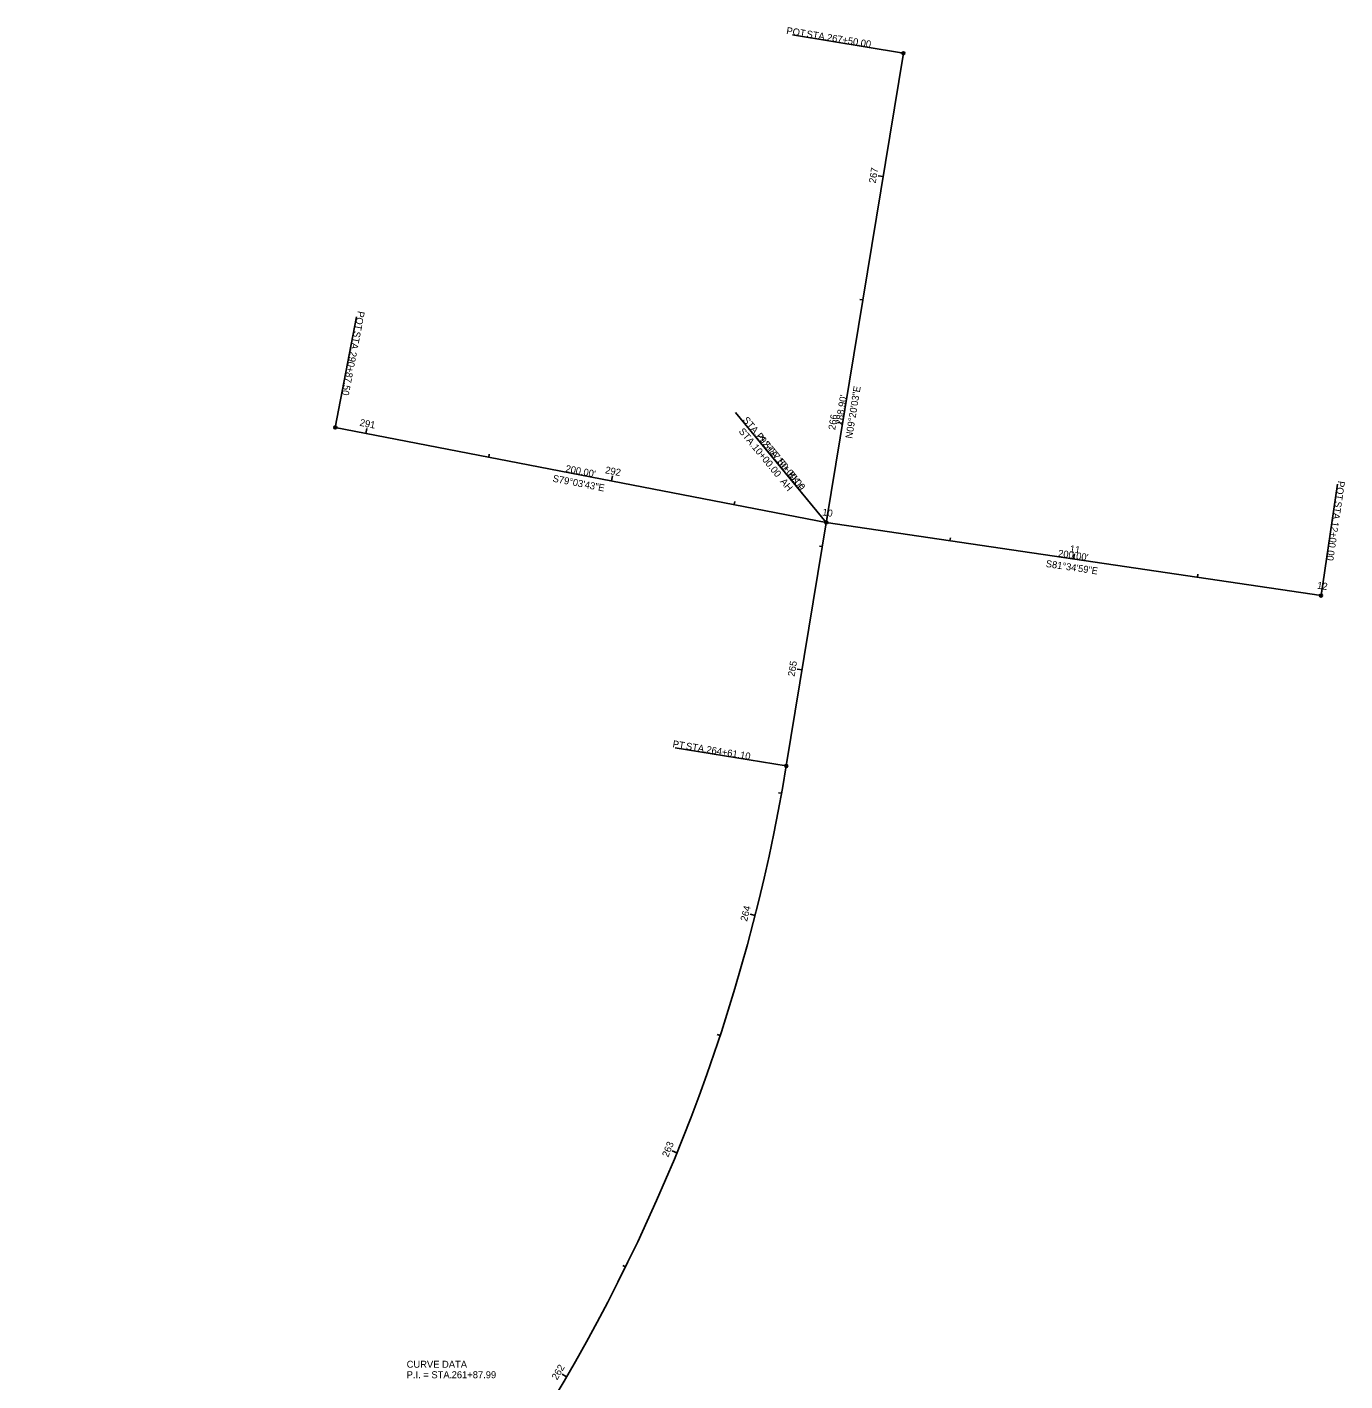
# Model space of a CAD drawing. Extents: x 1481464 to 1482480, y 364592 to 365678.
# Drawn here: x 1481953 to 1482480, y 365137 to 365678 of the extents above; entities that cross this region are included whole.
import ezdxf

# ---------------------------------------------------------------- set-up
doc = ezdxf.new("R2010")
doc.units = 0
for name, color, linetype in [('RD_X_Cells', 7, 'Continuous'), ('SG_X_Poles', 7, 'Continuous'), ('SN_X_Public', 7, 'Continuous'), ('SV_X_Random_Point', 7, 'Continuous'), ('UT_X_Electric_Cells', 7, 'Continuous'), ('UT_X_Misc_Cells', 7, 'Continuous')]:
    doc.layers.add(name, color=color, linetype=linetype)

msp = doc.modelspace()

# ---------------------------------------------------------------- linework, layer by layer
at = {"layer": 'RD_X_Cells'}
for p, q in [((1482303.1, 365667.88), (1482258.7, 365675.18)), ((1482075.9, 365518.19), (1482084.43, 365562.38)), ((1482272.26, 365480.24), (1482236, 365524.22)), ((1482272.26, 365480.24), (1482243.61, 365514.95)), ((1482470.11, 365450.97), (1482476.7, 365495.48)), ((1482256.25, 365382.8), (1482211.84, 365390.1))]:
    msp.add_line(p, q, dxfattribs=at)
for centre in [(1482303.1, 365667.88), (1482075.9, 365518.19), (1482272.26, 365480.24), (1482272.26, 365480.24), (1482470.11, 365450.97), (1482256.25, 365382.8)]:
    msp.add_circle(centre, 0.6, dxfattribs=at)
at = {"layer": 'SG_X_Poles'}
for p, q in [((1482303.1, 365667.88), (1482301.92, 365668.07)), ((1482294.99, 365618.54), (1482293.02, 365618.86)), ((1482286.88, 365569.2), (1482285.7, 365569.4)), ((1482088.17, 365515.82), (1482088.55, 365517.79)), ((1482278.77, 365519.86), (1482276.8, 365520.19)), ((1482137.26, 365506.33), (1482137.49, 365507.51)), ((1482186.35, 365496.85), (1482186.73, 365498.81)), ((1482235.44, 365487.36), (1482235.67, 365488.54)), ((1482272.26, 365480.24), (1482272.56, 365482.22)), ((1482321.72, 365472.93), (1482321.9, 365474.11)), ((1482270.67, 365470.52), (1482269.48, 365470.72)), ((1482371.19, 365465.61), (1482371.48, 365467.59)), ((1482420.65, 365458.29), (1482420.82, 365459.48)), ((1482470.11, 365450.97), (1482470.4, 365452.95)), ((1482262.56, 365421.19), (1482260.58, 365421.51)), ((1482254.36, 365371.86), (1482253.18, 365372.08)), ((1482243.78, 365323.01), (1482241.84, 365323.5)), ((1482229.81, 365275.01), (1482228.67, 365275.38)), ((1482212.53, 365228.1), (1482210.68, 365228.85)), ((1482192.02, 365182.51), (1482190.95, 365183.04)), ((1482168.38, 365138.46), (1482166.66, 365139.47))]:
    msp.add_line(p, q, dxfattribs=at)
at = {"layer": 'UT_X_Misc_Cells'}
for p, q in [((1482256.25, 365382.8), (1482303.1, 365667.88)), ((1482075.9, 365518.19), (1482272.26, 365480.24)), ((1482272.26, 365480.24), (1482470.11, 365450.97))]:
    msp.add_line(p, q, dxfattribs=at)
msp.add_arc((1481549.53, 365498.96), 716.2, 304.25163, 350.66585, dxfattribs=at)

# ---------------------------------------------------------------- texts
at = {"layer": 'RD_X_Cells'}
for s, rotation, p in [('POT', 350.6659, (1482256.14, 365675.63)), (' STA. ', 350.6659, (1482263.17, 365674.48)), ('267+50.00', 350.6659, (1482272.37, 365672.96)), ('POT', 259.062, (1482084.96, 365564.92)), (' STA. ', 259.062, (1482083.61, 365557.92)), ('290+87.50', 259.062, (1482081.84, 365548.77)), ('STA. ', 309.5057, (1482238.64, 365521.09)), ('STA. ', 309.5057, (1482237.07, 365516.56)), ('292+87.50', 309.5057, (1482243.93, 365514.66)), ('PI', 309.5057, (1482243.93, 365514.66)), ('10+00.00', 309.5057, (1482242.37, 365510.14)), (' STA. ', 309.5057, (1482246.04, 365512.1)), ('10+00.00', 309.5057, (1482251.97, 365504.91)), (' BK =', 309.5057, (1482255.97, 365500.06)), (' AH', 309.5057, (1482252.98, 365497.26)), ('POT', 261.5831, (1482476.95, 365496.95)), (' STA. ', 261.5831, (1482475.91, 365489.89)), ('12+00.00', 261.5831, (1482474.54, 365480.67)), ('PT', 350.6659, (1482210.65, 365390.33)), (' STA. ', 350.6659, (1482214.95, 365389.63)), ('264+61.10', 350.6659, (1482224.14, 365388.12))]:
    msp.add_text(s, height=2.8, rotation=rotation, dxfattribs=at).set_placement(p)
at = {"layer": 'SG_X_Poles'}
for s, rotation, p in [('267', 80.6659, (1482292, 365615.74)), ('291', 349.062, (1482085.48, 365518.89)), ('266', 80.6659, (1482275.78, 365517.06)), ('292', 349.062, (1482183.67, 365499.91)), ('10', 351.5831, (1482270.5, 365483.03)), ('11', 351.5831, (1482369.47, 365468.39)), ('12', 351.5831, (1482468.4, 365453.75)), ('265', 80.6659, (1482259.57, 365418.43)), ('264', 75.7779, (1482240.55, 365320.44)), ('263', 67.7779, (1482209.01, 365226.08)), ('262', 59.7779, (1482164.61, 365136.95))]:
    msp.add_text(s, height=2.8, rotation=rotation, dxfattribs=at).set_placement(p)
at = {"layer": 'SN_X_Public'}
for s, p in [('CURVE DATA', (1482104.44, 365142.09)), ('P.I. = STA. ', (1482104.44, 365137.89)), ('261+87.99', (1482122.43, 365137.89))]:
    msp.add_text(s, height=2.8, dxfattribs=at).set_placement(p)
at = {"layer": 'SV_X_Random_Point'}
for s, rotation, p in [('N09°20\'03"E', 80.6659, (1482282.61, 365513.59)), ('S79°03\'43"E', 349.062, (1482162.65, 365496.54)), ('S81°34\'59"E', 351.5831, (1482359.89, 365462.43))]:
    msp.add_text(s, height=2.8, rotation=rotation, dxfattribs=at).set_placement(p)
at = {"layer": 'UT_X_Electric_Cells'}
for s, rotation, p in [("288.90'", 80.6659, (1482278.59, 365518.99)), ("200.00'", 349.062, (1482167.77, 365500.48)), ("200.00'", 351.5831, (1482364.82, 365466.59))]:
    msp.add_text(s, height=2.8, rotation=rotation, dxfattribs=at).set_placement(p)

doc.saveas('drawing.dxf')
